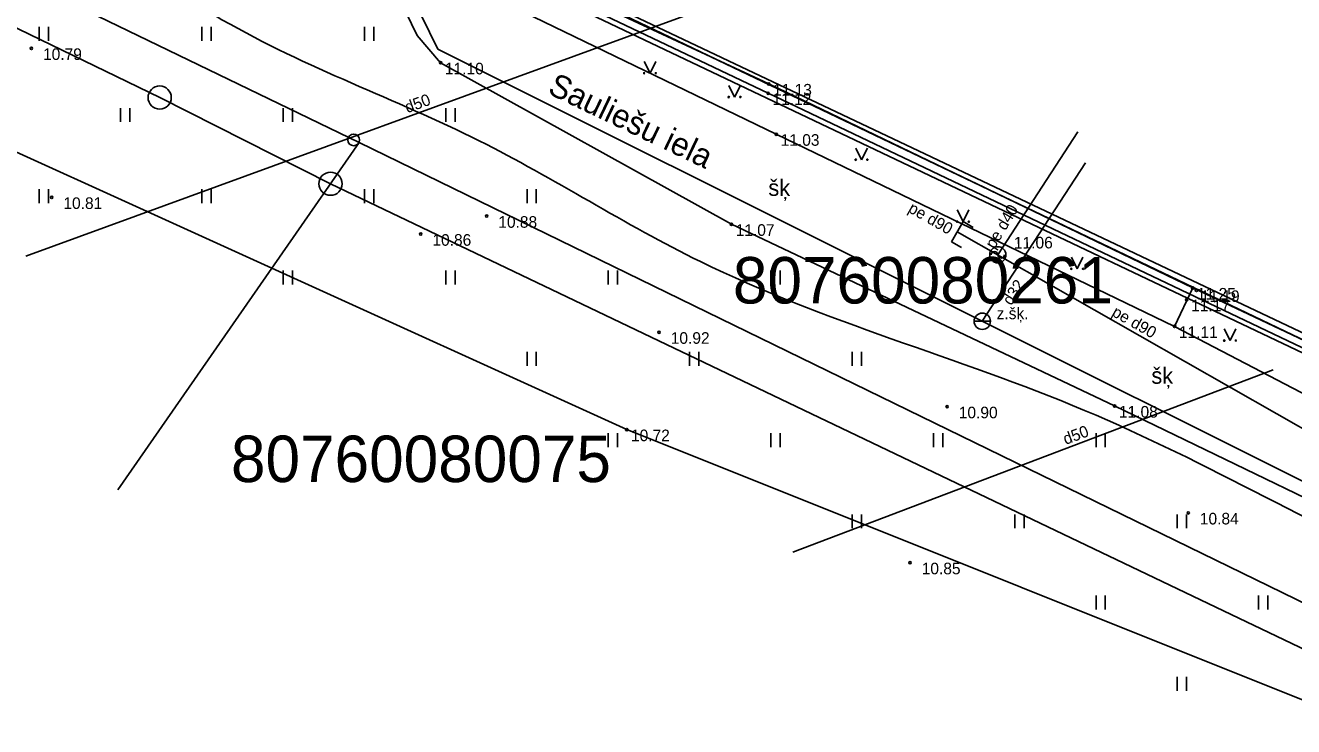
# Model space of a CAD drawing. Extents: x 503353 to 504004, y 304662 to 305049.
# Drawn here: x 503582.9 to 503637.5, y 304859 to 304889.2 of the extents above; entities that cross this region are included whole.
import ezdxf

# ---------------------------------------------------------------- set-up
doc = ezdxf.new("R2010")
doc.units = 0
for name, color, linetype in [('24', 7, 'Continuous'), ('59', 7, 'Continuous'), ('APGR_ELEM_####_####_#', 7, 'Continuous'), ('APGR_SARK_####_####_#', 7, 'Continuous'), ('BUVE_ELEM_####_####_#', 7, 'Continuous'), ('CELI_CAPM_####_####_#', 7, 'Continuous'), ('CELI_CMAL_####_####_#', 7, 'Continuous'), ('CELI_CSEG_####_TKST_#', 7, 'Continuous'), ('CELI_IELA_####_TKST_#', 7, 'Continuous'), ('DREN_VADP_####_####_#', 7, 'Continuous'), ('DREN_VADP_####_TKST_#', 7, 'Continuous'), ('ELEK_VADP_ZSPR_####_I', 7, 'Continuous'), ('GAZE_ELEM_####_####_#', 7, 'Continuous'), ('GAZE_ELEM_####_TKST_#', 7, 'Continuous'), ('GAZE_VADP_VSP2_####_I', 7, 'Continuous'), ('GAZE_VADP_VSP2_TKST_#', 7, 'Continuous'), ('GAZE_VADP_VSP2_TKST_I', 7, 'Continuous'), ('NORB_ZOGS_KBST_####_#', 7, 'Continuous'), ('NORB_ZOGS_ZSTP_####_#', 7, 'Continuous'), ('RAMI_UZMR_####_####_#', 7, 'Continuous'), ('RELJ_AATZ_####_TKST_#', 7, 'Continuous'), ('RELJ_ELEM_####_####_#', 7, 'Continuous'), ('RELJ_HORZ_PAMT_####_#', 7, 'Continuous'), ('TERT_ELEM_####_####_#', 7, 'Continuous'), ('TERT_KRND_####_####_#', 7, 'Continuous'), ('UDTK_ELEM_####_####_#', 7, 'Continuous'), ('UDTK_ELEM_####_TKST_#', 7, 'Continuous'), ('UDTK_VADP_UDEN_####_#', 7, 'Continuous'), ('UDTK_VADP_UDEN_TKST_#', 7, 'Continuous')]:
    doc.layers.add(name, color=color, linetype=linetype)

msp = doc.modelspace()

# ---------------------------------------------------------------- linework, layer by layer
at = {"layer": '24'}
for p, q in [((503427.051, 304966.576), (503597.271, 304884.111)), ((503624.198, 304882.173), (503602.955, 304892.334)), ((503597.271, 304884.111), (503586.884, 304869.155)), ((503597.271, 304884.111), (503674.34, 304846.523))]:
    msp.add_line(p, q, dxfattribs=at)
at = {"layer": 'APGR_ELEM_####_####_#'}
for p, q in [((503415.949, 304969.732), (503588.684, 304886.049)), ((503588.684, 304886.049), (503596.04, 304882.339))]:
    msp.add_line(p, q, dxfattribs=at)
for centre in [(503588.684, 304886.049), (503596.04, 304882.34)]:
    msp.add_circle(centre, 0.5, dxfattribs=at)
at = {"layer": 'APGR_SARK_####_####_#'}
for p, q in [((503608.368, 304889.745), (503663.371, 304863.436)), ((503596.04, 304882.339), (503658.194, 304852.61))]:
    msp.add_line(p, q, dxfattribs=at)
at = {"layer": 'BUVE_ELEM_####_####_#'}
msp.add_circle((503597.036, 304884.225), 0.25, dxfattribs=at)
at = {"layer": 'CELI_CAPM_####_####_#'}
for points in [[(503609.095, 304906.808), (503602.599, 304897.052), (503602.064, 304895.584), (503602.097, 304893.098), (503602.892, 304891.173), (503604.357, 304889.726), (503615.235, 304884.473)], [(503615.235, 304884.473), (503632.385, 304876.195), (503633.163, 304877.85)]]:
    msp.add_lwpolyline(points, dxfattribs=at)
at = {"layer": 'CELI_CMAL_####_####_#'}
for points in [[(503605.515, 304909.352), (503598.832, 304898.348), (503598.495, 304896.981), (503598.304, 304894.181), (503598.372, 304892.998), (503598.556, 304891.243), (503599.775, 304888.73), (503600.779, 304887.549), (503613.299, 304880.595)], [(503613.299, 304880.595), (503629.802, 304872.768), (503644.109, 304865.856), (503663.603, 304856.591), (503684.211, 304846.236), (503716.62, 304830.397), (503750.714, 304813.753), (503759.331, 304809.396), (503770.944, 304803.486), (503794.752, 304792.108), (503812.819, 304782.96), (503836.268, 304772.627), (503857.062, 304763.632), (503889.596, 304749.28)], [(503632.385, 304876.195), (503646.316, 304868.926), (503665.133, 304859.653), (503687.416, 304848.681)]]:
    msp.add_lwpolyline(points, dxfattribs=at)
at = {"layer": 'DREN_VADP_####_####_#'}
for p, q in [((503582.914, 304879.217), (503627.601, 304895.534)), ((503636.629, 304874.318), (503615.941, 304866.469))]:
    msp.add_line(p, q, dxfattribs=at)
at = {"layer": 'ELEK_VADP_ZSPR_####_I'}
msp.add_lwpolyline([(503602.234, 304892.027), (503656.944, 304865.995), (503664.699, 304862.319)], dxfattribs=at)
at = {"layer": 'GAZE_ELEM_####_####_#'}
for p, q in [((503623.274, 304880.708), (503622.778, 304879.84)), ((503623.708, 304880.461), (503623.274, 304880.708)), ((503623.213, 304879.592), (503622.778, 304879.84))]:
    msp.add_line(p, q, dxfattribs=at)
msp.add_circle((503624.772, 304879.278), 0.35, dxfattribs=at)
for centre, start, end in [((503624.632, 304879.278), 0, 180), ((503624.912, 304879.278), 180, 0)]:
    msp.add_arc(centre, 0.14, start, end, dxfattribs=at)
at = {"layer": 'GAZE_VADP_VSP2_####_I'}
for p, q in [((503624.772, 304879.278), (503628.222, 304884.58)), ((503623.026, 304880.274), (503661.15, 304858.537))]:
    msp.add_line(p, q, dxfattribs=at)
at = {"layer": 'NORB_ZOGS_KBST_####_#'}
for points in [[(503614.907, 304886.637), (503605.755, 304890.915), (503605.024, 304895.191), (503611.363, 304904.598)], [(503633.163, 304877.85), (503614.907, 304886.637)]]:
    msp.add_lwpolyline(points, dxfattribs=at)
at = {"layer": 'NORB_ZOGS_ZSTP_####_#'}
msp.add_lwpolyline([(503633.163, 304877.85), (503663.416, 304863.542), (503689.353, 304851.279)], dxfattribs=at)
at = {"layer": 'RAMI_UZMR_####_####_#'}
for points in [[(503407.219, 305023.925), (503368.776, 305020.183), (503379.431, 304977.462), (503383.452, 304957.421), (503396.867, 304960.598), (503416.959, 304959.032), (503433.698, 304951.36), (503608.791, 304871.751), (503642.724, 304858.177), (503694.651, 304834.724), (503842.283, 304765.867)], [(503825.923, 304784.828), (503697.433, 304847.709), (503608.51, 304889.842), (503606.524, 304897.202), (503679.244, 304999.942), (503684.897, 305009.76), (503666.777, 305017.939), (503656.134, 304996.39), (503644.103, 304987.6), (503600.987, 304924.263), (503587.985, 304916.668), (503422.237, 304989.372), (503408.615, 305023.495), (503368.776, 305020.183)]]:
    msp.add_lwpolyline(points, dxfattribs=at)
at = {"layer": 'RELJ_ELEM_####_####_#'}
for centre in [(503583.16, 304888.169), (503600.779, 304887.549), (503614.907, 304886.637), (503614.884, 304886.236), (503615.235, 304884.473), (503584.037, 304881.752), (503602.763, 304880.943), (503599.927, 304880.168), (503613.299, 304880.595), (503632.909, 304877.341), (503633.163, 304877.85), (503633.325, 304877.748), (503610.189, 304875.946), (503632.385, 304876.195), (503622.591, 304872.737), (503629.802, 304872.768), (503608.792, 304871.752), (503632.972, 304868.166), (503620.995, 304866.019)]:
    msp.add_circle(centre, 0.05, dxfattribs=at)
at = {"layer": 'RELJ_HORZ_PAMT_####_#'}
msp.add_spline([(503653.856, 304861.224), (503644.002, 304865.053), (503628.506, 304872.58), (503611.965, 304878.986), (503602.441, 304884.188), (503591.366, 304889.404), (503588.291, 304891.572), (503604.352, 304917.909), (503624.778, 304937.692)], degree=3, dxfattribs=at)
at = {"layer": 'TERT_ELEM_####_####_#'}
for p, q in [((503583.5, 304888.5), (503583.5, 304889.1)), ((503583.9, 304888.5), (503583.9, 304889.1)), ((503590.5, 304888.5), (503590.5, 304889.1)), ((503590.9, 304888.5), (503590.9, 304889.1)), ((503597.5, 304888.5), (503597.5, 304889.1)), ((503597.9, 304888.5), (503597.9, 304889.1)), ((503609.546, 304887.6), (503609.796, 304887.1)), ((503609.796, 304887.1), (503610.046, 304887.6)), ((503613.188, 304886.573), (503613.438, 304886.073)), ((503613.438, 304886.073), (503613.688, 304886.573)), ((503587, 304885), (503587, 304885.6)), ((503587.4, 304885), (503587.4, 304885.6)), ((503594, 304885), (503594, 304885.6)), ((503594.4, 304885), (503594.4, 304885.6)), ((503601, 304885), (503601, 304885.6)), ((503601.4, 304885), (503601.4, 304885.6)), ((503618.656, 304883.874), (503618.906, 304883.374)), ((503618.906, 304883.374), (503619.156, 304883.874)), ((503583.5, 304881.5), (503583.5, 304882.1)), ((503583.9, 304881.5), (503583.9, 304882.1)), ((503590.5, 304881.5), (503590.5, 304882.1)), ((503590.9, 304881.5), (503590.9, 304882.1)), ((503597.5, 304881.5), (503597.5, 304882.1)), ((503597.9, 304881.5), (503597.9, 304882.1)), ((503604.5, 304881.5), (503604.5, 304882.1)), ((503604.9, 304881.5), (503604.9, 304882.1)), ((503623.024, 304881.208), (503623.274, 304880.708)), ((503623.274, 304880.708), (503623.524, 304881.208)), ((503627.939, 304879.176), (503628.189, 304878.676)), ((503628.189, 304878.676), (503628.439, 304879.176)), ((503594, 304878), (503594, 304878.6)), ((503594.4, 304878), (503594.4, 304878.6)), ((503601, 304878), (503601, 304878.6)), ((503601.4, 304878), (503601.4, 304878.6)), ((503608, 304878), (503608, 304878.6)), ((503608.4, 304878), (503608.4, 304878.6)), ((503615, 304878), (503615, 304878.6)), ((503615.4, 304878), (503615.4, 304878.6)), ((503634.522, 304876.085), (503634.772, 304875.585)), ((503634.772, 304875.585), (503635.022, 304876.085)), ((503604.5, 304874.5), (503604.5, 304875.1)), ((503604.9, 304874.5), (503604.9, 304875.1)), ((503611.5, 304874.5), (503611.5, 304875.1)), ((503611.9, 304874.5), (503611.9, 304875.1)), ((503618.5, 304874.5), (503618.5, 304875.1)), ((503618.9, 304874.5), (503618.9, 304875.1)), ((503608, 304871), (503608, 304871.6)), ((503608.4, 304871), (503608.4, 304871.6)), ((503615, 304871), (503615, 304871.6)), ((503615.4, 304871), (503615.4, 304871.6)), ((503622, 304871), (503622, 304871.6)), ((503622.4, 304871), (503622.4, 304871.6)), ((503629, 304871), (503629, 304871.6)), ((503629.4, 304871), (503629.4, 304871.6)), ((503618.5, 304867.5), (503618.5, 304868.1)), ((503618.9, 304867.5), (503618.9, 304868.1)), ((503625.5, 304867.5), (503625.5, 304868.1)), ((503625.9, 304867.5), (503625.9, 304868.1)), ((503632.5, 304867.5), (503632.5, 304868.1)), ((503632.9, 304867.5), (503632.9, 304868.1)), ((503629, 304864), (503629, 304864.6)), ((503629.4, 304864), (503629.4, 304864.6)), ((503636, 304864), (503636, 304864.6)), ((503636.4, 304864), (503636.4, 304864.6)), ((503632.5, 304860.5), (503632.5, 304861.1)), ((503632.9, 304860.5), (503632.9, 304861.1))]:
    msp.add_line(p, q, dxfattribs=at)
for centre, radius in [((503609.546, 304887.099), 0.028), ((503610.046, 304887.099), 0.0263), ((503613.188, 304886.072), 0.028), ((503613.688, 304886.072), 0.0263), ((503618.656, 304883.374), 0.028), ((503619.156, 304883.374), 0.0263), ((503623.023, 304880.708), 0.028), ((503623.523, 304880.708), 0.0263), ((503627.939, 304878.675), 0.028), ((503628.439, 304878.675), 0.0263), ((503634.522, 304875.585), 0.028), ((503635.022, 304875.585), 0.0263)]:
    msp.add_circle(centre, radius, dxfattribs=at)
at = {"layer": 'TERT_KRND_####_####_#'}
for points in [[(503616.521, 304912.741), (503611.124, 304904.78), (503604.791, 304895.355), (503605.52, 304890.703), (503614.884, 304886.236)], [(503662.686, 304863.462), (503614.884, 304886.236)]]:
    msp.add_lwpolyline(points, dxfattribs=at)
at = {"layer": 'UDTK_ELEM_####_####_#'}
msp.add_line((503623.752, 304876.417), (503624.455, 304876.417), dxfattribs=at)
msp.add_circle((503624.104, 304876.417), 0.351, dxfattribs=at)
at = {"layer": 'UDTK_VADP_UDEN_####_#'}
msp.add_line((503624.104, 304876.417), (503628.547, 304883.246), dxfattribs=at)
for points in [[(503600.655, 304888.132), (503597.433, 304894.737)], [(503600.655, 304888.132), (503660.783, 304858.093)]]:
    msp.add_lwpolyline(points, dxfattribs=at)

# ---------------------------------------------------------------- texts
at = {"layer": '59'}
for s, p in [('80760080261', (503613.365, 304877.182)), ('80760080075', (503591.752, 304869.491))]:
    msp.add_text(s, height=2, dxfattribs=at).set_placement(p)
at = {"layer": 'CELI_CSEG_####_TKST_#'}
for p in [(503614.892, 304881.815), (503631.385, 304873.724)]:
    msp.add_text('šķ', height=0.7, dxfattribs=at).set_placement(p)
at = {"layer": 'CELI_IELA_####_TKST_#'}
msp.add_text('Sauliešu iela', height=1, rotation=334.4374, dxfattribs=at).set_placement((503605.345, 304886.243))
at = {"layer": 'DREN_VADP_####_TKST_#'}
for rotation, p in [(20.0598, (503599.348, 304885.377)), (20.777, (503627.694, 304871.089))]:
    msp.add_text('d50', height=0.5, rotation=rotation, dxfattribs=at).set_placement(p)
at = {"layer": 'GAZE_ELEM_####_TKST_#'}
msp.add_text('11.06', height=0.5, rotation=0.3034, dxfattribs=at).set_placement((503625.467, 304879.547))
at = {"layer": 'GAZE_VADP_VSP2_TKST_#'}
for p in [(503620.873, 304881.144), (503629.642, 304876.674)]:
    msp.add_text('pe d90', height=0.5, rotation=330.3098, dxfattribs=at).set_placement(p)
at = {"layer": 'GAZE_VADP_VSP2_TKST_I'}
msp.add_text('pe d40', height=0.5, rotation=58.9102, dxfattribs=at).set_placement((503624.619, 304879.497))
at = {"layer": 'RELJ_AATZ_####_TKST_#'}
for s, p in [('10.79', (503583.66, 304887.669)), (' 11.10', (503600.779, 304887.049)), (' 11.12', (503614.884, 304885.736)), (' 11.13', (503614.907, 304886.137)), (' 11.03', (503615.235, 304883.973)), ('10.81', (503584.537, 304881.252)), ('10.88', (503603.263, 304880.443)), ('10.86', (503600.427, 304879.668)), (' 11.07', (503613.299, 304880.095)), (' 11.25', (503633.163, 304877.35)), (' 11.19', (503633.325, 304877.248)), (' 11.17', (503632.909, 304876.841)), ('10.92', (503610.689, 304875.446)), (' 11.11', (503632.385, 304875.695)), ('10.90', (503623.091, 304872.237)), (' 11.08', (503629.802, 304872.268)), (' 10.72', (503608.791, 304871.251)), ('10.84', (503633.472, 304867.666)), ('10.85', (503621.495, 304865.519))]:
    msp.add_text(s, height=0.5, dxfattribs=at).set_placement(p)
at = {"layer": 'UDTK_ELEM_####_TKST_#'}
msp.add_text('z.šķ.', height=0.5, dxfattribs=at).set_placement((503624.721, 304876.506))
at = {"layer": 'UDTK_VADP_UDEN_TKST_#'}
msp.add_text('d32', height=0.5, rotation=56.9508, dxfattribs=at).set_placement((503625.349, 304877.064))

doc.saveas('drawing.dxf')
